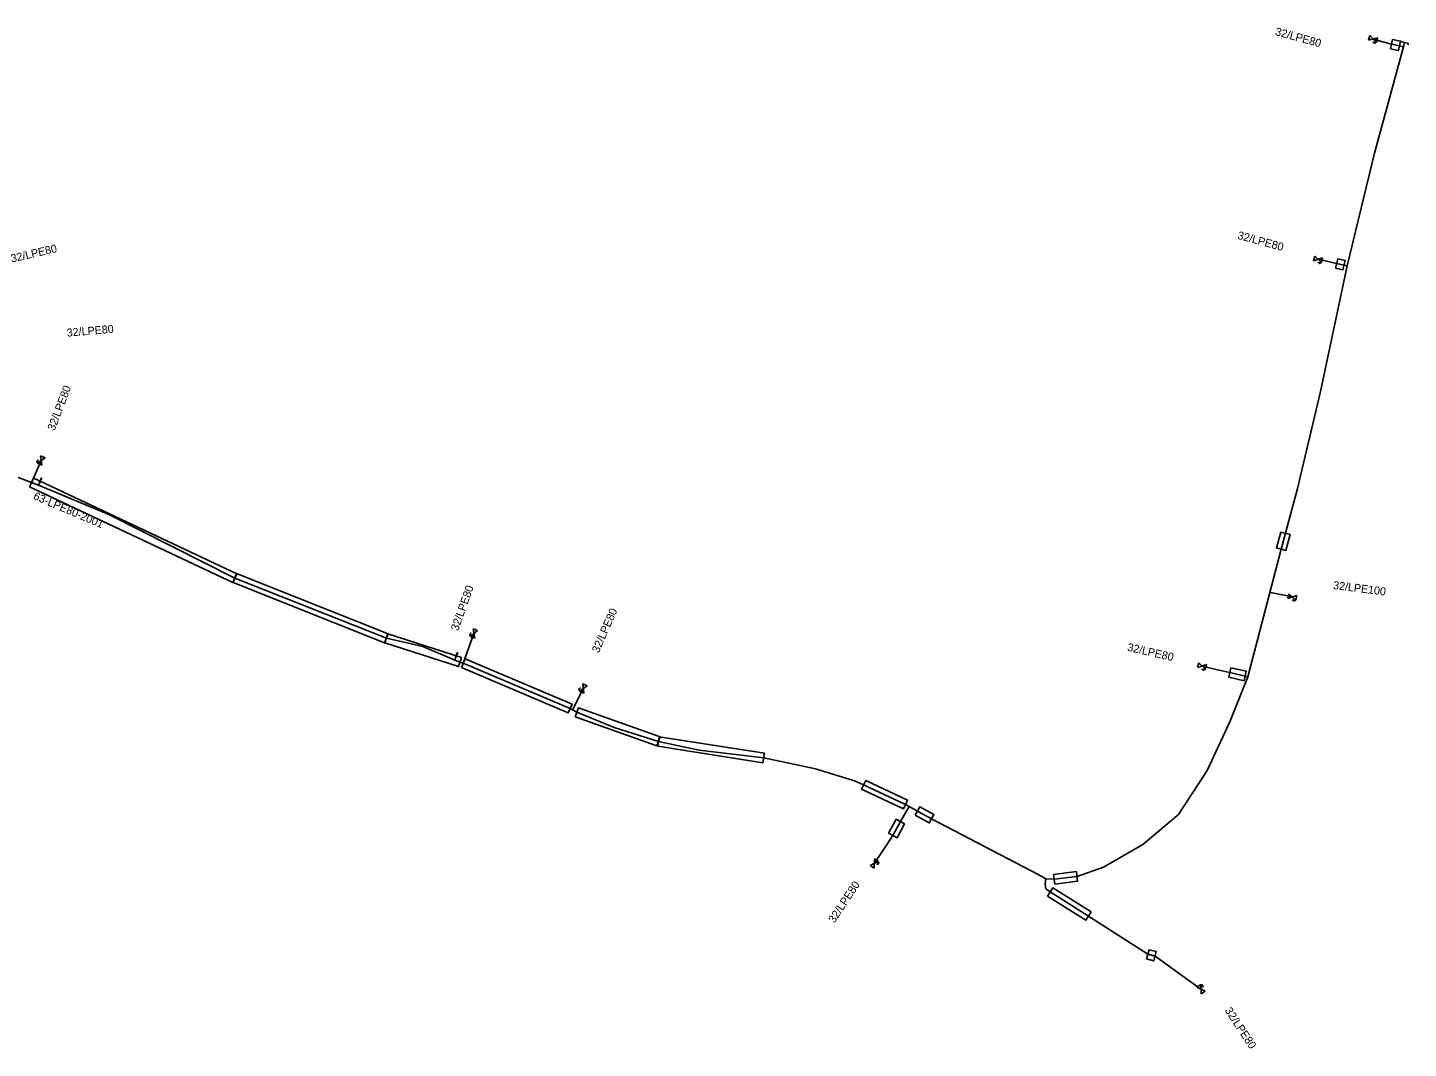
# Model space of a CAD drawing. Extents: x -787723 to -786204, y -1153846 to -1152384.
# Drawn here: x -786376.3 to -786203.7, y -1153558.1 to -1153430.5 of the extents above; entities that cross this region are included whole.
import ezdxf

# ---------------------------------------------------------------- set-up
doc = ezdxf.new("R2010")
doc.units = 0
for name, color, linetype in [('Vrstva 1', 7, 'Continuous'), ('Vrstva 21', 7, 'Continuous'), ('Vrstva 22', 7, 'Continuous'), ('Vrstva 28', 7, 'Continuous'), ('Vrstva 29', 7, 'Continuous'), ('Vrstva 31', 7, 'Continuous'), ('Vrstva 32', 7, 'Continuous')]:
    doc.layers.add(name, color=color, linetype=linetype)

# ---------------------------------------------------------------- blocks, each defined once
blk = doc.blocks.new('DEC063-SN')
at = {"layer": 'Vrstva 1'}
for p, q in [((-0.5, -0.3), (0.5, 0.3)), ((0.5, -0.3), (-0.5, 0.3)), ((-0.5, 0.3), (-0.5, -0.3)), ((0.5, 0.3), (0.5, -0.3)), ((0.126, -0.318), (0.126, -0.458)), ((0.126, -0.384), (0.206, -0.384)), ((0.206, -0.458), (0.206, -0.318)), ((0.366, -0.458), (0.366, -0.318))]:
    blk.add_line(p, q, dxfattribs=at)
for points in [[(0.246, -0.318), (0.246, -0.418), (0.252, -0.438), (0.264, -0.451), (0.281, -0.458), (0.292, -0.458), (0.309, -0.451), (0.321, -0.438), (0.326, -0.418), (0.326, -0.318)], [(0.366, -0.318), (0.418, -0.318), (0.435, -0.325), (0.441, -0.331), (0.446, -0.344), (0.446, -0.364), (0.441, -0.378), (0.435, -0.384), (0.418, -0.391), (0.366, -0.391)]]:
    blk.add_lwpolyline(points, dxfattribs=at)
blk = doc.blocks.new('DEC130')
at = {"layer": 'Vrstva 1'}
blk.add_lwpolyline([(0.2, 0.5), (0, 0.5), (0, -0.5), (0.2, -0.5)], dxfattribs=at)
blk = doc.blocks.new('DEC127')
at = {"layer": 'Vrstva 1'}
for p, q in [((0, 0.56), (0, 0.99)), ((0, 0.42), (0, -0.01))]:
    blk.add_line(p, q, dxfattribs=at)
blk.add_lwpolyline([(-0.07, 0.82), (0, 0.99), (0.07, 0.82)], dxfattribs=at)
blk.add_circle((0, 0.49), 0.07, dxfattribs=at)

msp = doc.modelspace()

# ---------------------------------------------------------------- linework, layer by layer
at = {"layer": 'Vrstva 21'}
msp.add_lwpolyline([(-786379.38, -1153485.98), (-786375.75, -1153487.36), (-786374.9, -1153487.72), (-786366.11, -1153491.36), (-786350.36, -1153499.32), (-786331.43, -1153506.83), (-786326.86, -1153507.88), (-786322.88, -1153509.55), (-786322.23, -1153509.81), (-786321.81, -1153509.94), (-786308.46, -1153515.62), (-786308.16, -1153515.79), (-786307.64, -1153516.08), (-786302.98, -1153517.98), (-786297.42, -1153519.72), (-786292.33, -1153520.83), (-786284.28, -1153521.79), (-786277.81, -1153523.13), (-786272.92, -1153524.65), (-786271.79, -1153525.15), (-786266.57, -1153527.62), (-786266.11, -1153527.87), (-786265.06, -1153528.42), (-786263.31, -1153529.38), (-786250, -1153536.36), (-786249.01, -1153536.88), (-786247.97, -1153536.95), (-786245.13, -1153536.59), (-786241.83, -1153535.44), (-786236.91, -1153532.58), (-786232.46, -1153528.87), (-786228.85, -1153523.35), (-786226.05, -1153517.28), (-786223.77, -1153511.66), (-786219.63, -1153495.69), (-786219.08, -1153493.72), (-786217.59, -1153488.14), (-786214.69, -1153476), (-786211.38, -1153460.31), (-786207.95, -1153446.23), (-786204.33, -1153432.96), (-786204.21, -1153432.39)], dxfattribs=at)
at = {"layer": 'Vrstva 29'}
for points in [[(-786205.97, -1153433.19), (-786205.71, -1153432.01), (-786204.71, -1153432.23), (-786204.97, -1153433.41)], [(-786212.84, -1153460.58), (-786212.54, -1153459.42), (-786211.61, -1153459.66), (-786211.91, -1153460.82)], [(-786376.01, -1153487.9), (-786375.49, -1153486.82), (-786350.1, -1153498.78), (-786350.61, -1153499.86)], [(-786219.66, -1153493.56), (-786218.5, -1153493.88), (-786219.05, -1153495.85), (-786220.21, -1153495.53)], [(-786350.58, -1153499.88), (-786350.14, -1153498.76), (-786331.21, -1153506.27), (-786331.65, -1153507.39)], [(-786331.61, -1153507.4), (-786331.24, -1153506.26), (-786322.05, -1153509.24), (-786322.41, -1153510.38)], [(-786322.04, -1153510.49), (-786321.58, -1153509.39), (-786308.22, -1153515.07), (-786308.69, -1153516.17)], [(-786226.18, -1153511.71), (-786225.92, -1153510.53), (-786223.99, -1153510.96), (-786224.25, -1153512.14)], [(-786307.84, -1153516.65), (-786307.44, -1153515.51), (-786297.22, -1153519.15), (-786297.62, -1153520.28)], [(-786297.51, -1153520.31), (-786297.33, -1153519.13), (-786284.19, -1153521.2), (-786284.37, -1153522.38)], [(-786272.05, -1153525.69), (-786271.53, -1153524.61), (-786266.31, -1153527.08), (-786266.83, -1153528.16)], [(-786267.73, -1153529.45), (-786266.67, -1153530.03), (-786267.61, -1153531.75), (-786268.67, -1153531.17)], [(-786265.35, -1153528.95), (-786264.77, -1153527.89), (-786263.02, -1153528.85), (-786263.6, -1153529.91)], [(-786247.89, -1153537.54), (-786248.05, -1153536.35), (-786245.21, -1153535.99), (-786245.05, -1153537.19)], [(-786248.8, -1153539.04), (-786248.16, -1153538.02), (-786243.37, -1153541.03), (-786244.01, -1153542.05)], [(-786236.43, -1153546.9), (-786236.11, -1153545.74), (-786235.22, -1153545.98), (-786235.54, -1153547.14)]]:
    msp.add_lwpolyline(points, close=True, dxfattribs=at)
at = {"layer": 'Vrstva 31'}
for points in [[(-786204.33, -1153432.96), (-786204.84, -1153432.82), (-786205.84, -1153432.6), (-786208.13, -1153431.97)], [(-786211.38, -1153460.31), (-786211.76, -1153460.24), (-786212.69, -1153460), (-786215.01, -1153459.49)], [(-786375.75, -1153487.36), (-786375.35, -1153486.47), (-786374.55, -1153484.64)], [(-786221.03, -1153501.08), (-786220.94, -1153501.11), (-786218.22, -1153501.67)], [(-786321.81, -1153509.94), (-786321.15, -1153508.11), (-786320.48, -1153506.23)], [(-786223.77, -1153511.66), (-786224.12, -1153511.55), (-786226.05, -1153511.12), (-786227.56, -1153510.76), (-786229.51, -1153510.31)], [(-786308.16, -1153515.79), (-786307.71, -1153514.89), (-786306.83, -1153513.1)], [(-786266.11, -1153527.87), (-786267.2, -1153529.74), (-786268.14, -1153531.46), (-786269.36, -1153533.31), (-786270.46, -1153534.97)], [(-786249.01, -1153536.88), (-786249.12, -1153537.52), (-786249.02, -1153538.12), (-786248.48, -1153538.53), (-786243.69, -1153541.54), (-786236.27, -1153546.32), (-786235.38, -1153546.56), (-786229.64, -1153550.69)]]:
    msp.add_lwpolyline(points, dxfattribs=at)

# ---------------------------------------------------------------- block references
at = {"layer": 'Vrstva 22', "rotation": -104.71422773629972}
msp.add_blockref('DEC130', (-786204.21, -1153432.39), dxfattribs=at)
at = {"layer": 'Vrstva 28'}
for p, rotation in [((-786374.9, -1153487.72), -22.48445825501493), ((-786322.88, -1153509.55), -20.274597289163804)]:
    msp.add_blockref('DEC127', p, dxfattribs=dict(at, rotation=rotation))
at = {"layer": 'Vrstva 32'}
for p, rotation in [((-786208.13, -1153431.97), -15.382066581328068), ((-786215.01, -1153459.49), -12.3979972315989), ((-786374.55, -1153484.64), -113.5187889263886), ((-786218.22, -1153501.67), -11.928094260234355), ((-786320.48, -1153506.23), -109.93837776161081), ((-786229.51, -1153510.31), -12.994616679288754), ((-786306.83, -1153513.1), -114.39976938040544), ((-786270.46, -1153534.97), 56.46953053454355), ((-786229.64, -1153550.69), 123.96031663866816)]:
    msp.add_blockref('DEC063-SN', p, dxfattribs=dict(at, rotation=rotation))

# ---------------------------------------------------------------- texts
at = {"layer": 'Vrstva 21'}
msp.add_text('63-LPE80-2001', height=1, rotation=336.81, dxfattribs=at).set_placement((-786375.63, -1153489.42))
at = {"layer": 'Vrstva 31'}
for s, rotation, p in [('32/LPE80', 344.618, (-786220.44, -1153431.46)), ('32/LPE80', 344.802, (-786225.14, -1153456.92)), ('32/LPE80', 13.035, (-786378.23, -1153459.9)), ('32/LPE80', 4.786, (-786371.32, -1153469.16)), ('32/LPE80', 69.082, (-786372.89, -1153480.98)), ('32/LPE100', 352.72, (-786213.17, -1153500.67)), ('32/LPE80', 70.385, (-786322.47, -1153505.98)), ('32/LPE80', 66.412, (-786304.89, -1153508.74)), ('32/LPE80', 347.005, (-786238.91, -1153508.38)), ('32/LPE80', 56.47, (-786275.45, -1153542.49)), ('32/LPE80', 303.248, (-786226.71, -1153553.33))]:
    msp.add_text(s, height=1, rotation=rotation, dxfattribs=at).set_placement(p)

doc.saveas('drawing.dxf')
